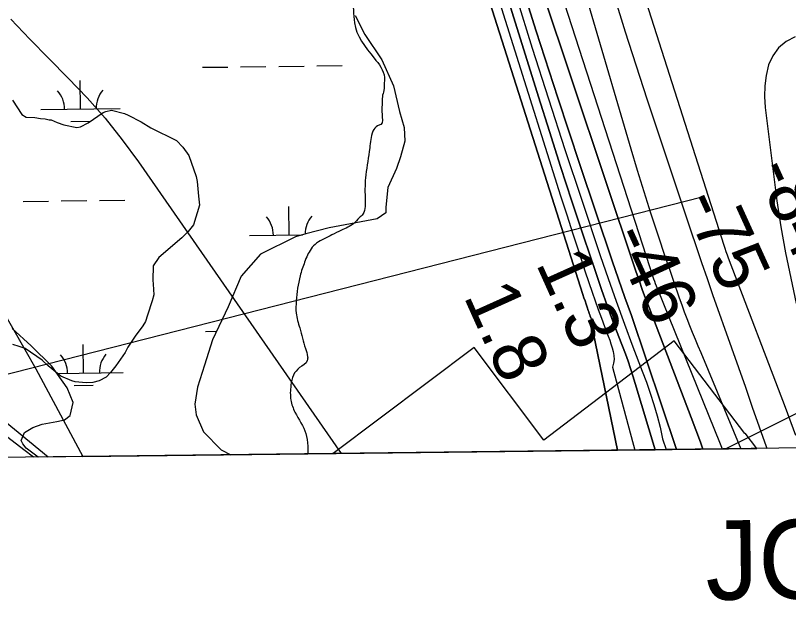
# Model space of a CAD drawing. Extents: x 3694830 to 3732949, y 415201 to 440970.
# Drawn here: x 3716600 to 3717574, y 420616 to 421382 of the extents above; entities that cross this region are included whole.
import ezdxf

# ---------------------------------------------------------------- set-up
doc = ezdxf.new("R2010")
doc.units = 0
for name, color, linetype in [('V-ANNO-TEXT', 7, 'Continuous'), ('V-GRID-FRAM', 7, 'Continuous'), ('V-LEVE-TOET', 7, 'Continuous'), ('V-RIVR-EDGE', 7, 'Continuous'), ('V-RIVR-RANG', 7, 'Continuous'), ('V-RRAP-FSHR', 7, 'Continuous'), ('V-RRAP-RVMT', 7, 'Continuous'), ('V-SITE-VEGE', 7, 'Continuous'), ('V-TOPO-DPTH', 7, 'Continuous'), ('V-TOPO-MAJR', 7, 'Continuous'), ('V-TOPO-MINR', 7, 'Continuous'), ('V-TOPO-WATR', 7, 'Continuous'), ('V-UTIL-LINE', 7, 'Continuous'), ('V-WETL-SWMP', 7, 'Continuous')]:
    doc.layers.add(name, color=color, linetype=linetype)

msp = doc.modelspace()

# ---------------------------------------------------------------- linework, layer by layer
at = {"layer": 'V-GRID-FRAM'}
msp.add_lwpolyline([(3698844.69, 438797.54), (3730590.83, 439176.18), (3730815.62, 420995.11), (3699053.61, 420616.27), (3698844.69, 438797.54)], dxfattribs=at)
at = {"layer": 'V-LEVE-TOET'}
msp.add_lwpolyline([(3716622.87, 420825.82), (3716610.62, 420835.27), (3716590.4, 420850.54)], dxfattribs=at)
at = {"layer": 'V-RIVR-EDGE'}
msp.add_spline([(3716802.17, 421670.49), (3716830.83, 421648.17), (3716851, 421630.33), (3716868.75, 421613.31), (3716887.31, 421596.28), (3716893.75, 421584.94), (3716901.39, 421566.72), (3716910.66, 421552.55), (3716931.23, 421530.25), (3716962.26, 421490.95), (3716975.56, 421470.7), (3716989.66, 421451.26), (3717004.98, 421432.21), (3717019.08, 421411.56), (3717025.9, 421389.3), (3717027.08, 421373.12), (3717052.04, 421328.58), (3717064.92, 421304.29), (3717064.91, 421300.24), (3717064.07, 421287.71), (3717062.43, 421280.03), (3717062, 421269.52), (3717061.97, 421257.79), (3717060.32, 421244.85), (3717056.27, 421243.25), (3717050.6, 421236.39), (3717046.5, 421215.37), (3717041.56, 421181.42), (3717040.68, 421152.71), (3717037.8, 421132.09), (3717033.34, 421127.25), (3717026.45, 421120.39), (3717010.26, 421111.54), (3716998.92, 421105.9), (3716989.2, 421101.07), (3716979.48, 421095.44), (3716972.59, 421088.18), (3716964.46, 421071.62), (3716958.76, 421054.24), (3716953.83, 421022.71), (3716953.79, 421007.35), (3716958.19, 420988.74), (3716965.41, 420962.84), (3716968.21, 420952.32), (3716967.79, 420947.47), (3716958.07, 420938.6), (3716950.36, 420929.31), (3716947.1, 420916.38), (3716947.05, 420897.78), (3716952.27, 420882.4), (3716965.95, 420855.68), (3716968.34, 420839.9), (3716968.61, 420829.95)], degree=3, dxfattribs=at)
at = {"layer": 'V-RIVR-RANG'}
msp.add_line((3716496.26, 420907.04), (3717465.33, 421153.8), dxfattribs=at)
at = {"layer": 'V-RRAP-FSHR'}
for points in [[(3716641.15, 420826.04), (3716497.1, 420943.72), (3716411.63, 421060.5), (3716364.3, 421170.5), (3716321.83, 421303.9), (3716285.1, 421373.79), (3716186.8, 421473.87), (3716066.75, 421590.93), (3715980.47, 421690.03), (3715930.26, 421828.72), (3715913.48, 421896.78), (3715879.02, 422073.91), (3715879.91, 422256.34), (3715873.14, 422428), (3715914.01, 422633.62), (3716031.29, 423135.79), (3716104.08, 423396.54), (3716111.44, 423811.54), (3716102.74, 424148.37), (3716065.57, 424473.12), (3715995.1, 425269.77), (3715894.16, 426351.13), (3715758.55, 427758.05)], [(3716641.15, 420826.04), (3716586.88, 420870.38)]]:
    msp.add_lwpolyline(points, dxfattribs=at)
at = {"layer": 'V-RRAP-RVMT'}
for p, q in [((3717430.39, 420972.28), (3717266.02, 420847.26)), ((3717519.25, 420855.5), (3717430.39, 420972.28)), ((3717178.14, 420964.06), (3717000.43, 420830.33)), ((3717266.02, 420847.26), (3717178.14, 420964.06)), ((3717519.75, 420855.88), (3717519.25, 420855.5)), ((3717534.34, 420836.7), (3717519.75, 420855.88)), ((3717000.43, 420830.33), (3717534.34, 420836.7))]:
    msp.add_line(p, q, dxfattribs=at)
at = {"layer": 'V-SITE-VEGE'}
msp.add_lwpolyline([(3716596.03, 421275.37), (3716607.79, 421257.42), (3716613.36, 421254.32), (3716624.51, 421253.7), (3716631.32, 421252.46), (3716637.51, 421251.84), (3716642.46, 421250.6), (3716644.94, 421250.6), (3716652.37, 421247.51), (3716661.03, 421244.41), (3716677.13, 421241.31), (3716682.08, 421241.93), (3716691.37, 421246.88), (3716710.56, 421259.88), (3716713.66, 421261.12), (3716721.09, 421262.98), (3716737.19, 421258.64), (3716742.14, 421256.79), (3716758.23, 421248.12), (3716770.62, 421240.68), (3716802.81, 421224.58), (3716810.86, 421216.54), (3716818.29, 421206.01), (3716827.57, 421179.39), (3716828.81, 421173.2), (3716830.66, 421154.62), (3716831.9, 421143.48), (3716824.47, 421118.71), (3716817.66, 421110.05), (3716809.61, 421102), (3716780.51, 421077.24), (3716773.7, 421066.71), (3716773.07, 421048.76), (3716773.7, 421043.8), (3716774.31, 421030.18), (3716772.45, 421022.76), (3716766.26, 421004.8), (3716763.78, 420996.75), (3716760.69, 420991.18), (3716750.78, 420978.18), (3716741.49, 420964.56), (3716738.39, 420957.75), (3716726.63, 420941.04), (3716719.82, 420932.37), (3716714.25, 420926.8), (3716705.58, 420921.85), (3716697.53, 420919.99), (3716688.86, 420919.37), (3716675.24, 420920.61), (3716670.91, 420921.85), (3716657.29, 420928.04), (3716652.96, 420931.14), (3716641.19, 420941.04), (3716633.76, 420947.85), (3716612.1, 420962.72), (3716604.67, 420965.19), (3716596.62, 420967.67)], dxfattribs=at)
at = {"layer": 'V-TOPO-DPTH'}
msp.add_line((3717358.94, 420834.6), (3717406.36, 420835.17), dxfattribs=at)
for points in [[(3716812.13, 422663.78), (3716033.9, 421927.76), (3716054.45, 421877.33), (3716064.68, 421852.1), (3716074.85, 421826.84), (3716084.93, 421801.55), (3716094.94, 421776.23), (3716145.42, 421647.95), (3716152.26, 421632.9), (3716160.08, 421618.43), (3716169.35, 421604.85), (3716179.58, 421591.85), (3716198.72, 421570), (3716218.89, 421546.23), (3716238.56, 421522.06), (3716257.47, 421497.3), (3716275.87, 421472.14), (3716402.32, 421293.59), (3716480.92, 421177.25), (3716555.98, 421058.78), (3716625.75, 420937.12), (3716684.91, 420826.56), (3717358.94, 420834.6)], [(3717052.46, 422162.67), (3717076.62, 422065.19), (3717101.54, 421967.9), (3717145.88, 421798.91), (3717149.26, 421786.27), (3717152.71, 421773.64), (3717156.29, 421761.05), (3717159.95, 421748.48), (3717187.93, 421653.93), (3717205.95, 421594.2), (3717224.38, 421534.6), (3717243.45, 421475.21), (3717262.94, 421415.94), (3717382.01, 421060.22), (3717385.96, 421048.66), (3717390.01, 421037.13), (3717394.21, 421025.66), (3717398.52, 421014.22), (3717451.56, 420875.9), (3717463.31, 420844.57), (3717466.51, 420835.89)], [(3717466.51, 420835.89), (3717463.31, 420844.57), (3717451.56, 420875.9), (3717398.52, 421014.22), (3717394.21, 421025.66), (3717390.01, 421037.13), (3717385.96, 421048.66), (3717382.01, 421060.22), (3717262.94, 421415.94), (3717243.45, 421475.21), (3717224.38, 421534.6), (3717205.95, 421594.2), (3717187.93, 421653.93), (3717159.95, 421748.48), (3717156.29, 421761.05), (3717152.71, 421773.64), (3717149.26, 421786.27), (3717145.88, 421798.91), (3717101.54, 421967.9), (3717076.62, 422065.19), (3717052.46, 422162.67)], [(3717087.33, 422109.05), (3717169.89, 421783.26), (3717170.75, 421779.93), (3717171.63, 421776.6), (3717172.54, 421773.29), (3717173.48, 421769.97), (3717181.43, 421742.2), (3717186.45, 421725.02), (3717191.58, 421707.89), (3717196.89, 421690.81), (3717202.31, 421673.77), (3717404.25, 421050.56), (3717405.26, 421047.54), (3717406.32, 421044.53), (3717407.45, 421041.54), (3717408.62, 421038.58), (3717488.3, 420842.58), (3717490.85, 420836.18)], [(3717087.33, 422109.05), (3717169.89, 421783.26), (3717170.75, 421779.93), (3717171.63, 421776.6), (3717172.54, 421773.29), (3717173.48, 421769.97), (3717181.43, 421742.2), (3717186.45, 421725.02), (3717191.58, 421707.89), (3717196.89, 421690.81), (3717202.31, 421673.77), (3717404.25, 421050.56), (3717405.26, 421047.54), (3717406.32, 421044.53), (3717407.45, 421041.54), (3717408.62, 421038.58), (3717488.3, 420842.58), (3717490.85, 420836.18)], [(3717042.79, 422099.17), (3717060.2, 422033.32), (3717077.77, 421967.5), (3717095.45, 421901.72), (3717118.46, 421816.52), (3717124.83, 421793.39), (3717131.34, 421770.3), (3717138.07, 421747.28), (3717144.95, 421724.29), (3717203.62, 421531.46), (3717229.72, 421446.99), (3717256.29, 421362.67), (3717283.57, 421278.58), (3717311.33, 421194.64), (3717352.04, 421073.27), (3717359.95, 421050.19), (3717368.05, 421027.17), (3717376.45, 421004.26), (3717433.29, 420835.49)], [(3717433.29, 420835.49), (3717376.45, 421004.26), (3717368.05, 421027.17), (3717359.95, 421050.19), (3717352.04, 421073.27), (3717311.33, 421194.64), (3717283.57, 421278.58), (3717256.29, 421362.67), (3717229.72, 421446.99), (3717203.62, 421531.46), (3717144.95, 421724.29), (3717138.07, 421747.28), (3717131.34, 421770.3), (3717124.83, 421793.39), (3717118.46, 421816.52), (3717095.45, 421901.72), (3717077.77, 421967.5), (3717060.2, 422033.32), (3717042.79, 422099.17)], [(3717084.18, 421756.32), (3717315.28, 421030.69), (3717316.56, 421026.72), (3717317.85, 421022.74), (3717319.16, 421018.78), (3717320.48, 421014.81), (3717321.92, 421010.56), (3717322.55, 421008.73), (3717323.19, 421006.91), (3717323.85, 421005.1), (3717324.53, 421003.29), (3717325.34, 421001.2), (3717325.61, 421000.43), (3717325.87, 420999.66), (3717326.09, 420998.89), (3717326.3, 420998.1), (3717326.35, 420997.35), (3717326.27, 420996.64), (3717325.96, 420995.99), (3717325.52, 420995.38), (3717358.94, 420834.6)], [(3717358.94, 420834.6), (3717325.52, 420995.38), (3717325.96, 420995.99), (3717326.27, 420996.64), (3717326.35, 420997.35), (3717326.3, 420998.1), (3717326.09, 420998.89), (3717325.87, 420999.66), (3717325.61, 421000.43), (3717325.34, 421001.2), (3717324.53, 421003.29), (3717323.85, 421005.1), (3717323.19, 421006.91), (3717322.55, 421008.73), (3717321.92, 421010.56), (3717320.48, 421014.81), (3717319.16, 421018.78), (3717317.85, 421022.74), (3717316.56, 421026.72), (3717315.28, 421030.69), (3717084.18, 421756.32)], [(3717406.36, 420835.17), (3717380.89, 420918.72), (3717378.2, 420928.11), (3717375.31, 420937.44), (3717372.14, 420946.68), (3717368.78, 420955.85), (3717360.57, 420977.27), (3717353.09, 420997.15), (3717345.77, 421017.09), (3717338.71, 421037.13), (3717331.82, 421057.22), (3717315.97, 421104.37), (3717301.43, 421148.14), (3717287.07, 421191.96), (3717273.01, 421235.88), (3717259.14, 421279.86), (3717128.68, 421698.31)], [(3717406.36, 420835.17), (3717380.89, 420918.72), (3717378.2, 420928.11), (3717375.31, 420937.44), (3717372.14, 420946.68), (3717368.78, 420955.85), (3717360.57, 420977.27), (3717353.09, 420997.15), (3717345.77, 421017.09), (3717338.71, 421037.13), (3717331.82, 421057.22), (3717315.97, 421104.37), (3717301.43, 421148.14), (3717287.07, 421191.96), (3717273.01, 421235.88), (3717259.14, 421279.86), (3717128.68, 421698.31)]]:
    msp.add_lwpolyline(points, dxfattribs=at)
at = {"layer": 'V-TOPO-MAJR'}
msp.add_lwpolyline([(3717228.21, 421715.89), (3717375.73, 421214.18), (3717383.79, 421187.31), (3717392.04, 421160.51), (3717400.57, 421133.79), (3717409.29, 421107.13), (3717419.51, 421076.47), (3717423.3, 421065.2), (3717427.13, 421053.94), (3717431.02, 421042.7), (3717434.95, 421031.48), (3717436.7, 421026.51), (3717439.83, 421017.8), (3717443.03, 421009.11), (3717446.33, 421000.46), (3717449.69, 420991.84), (3717453.12, 420983.25), (3717456.59, 420974.66), (3717460.1, 420966.1), (3717463.64, 420957.55), (3717514.19, 420836.46)], dxfattribs=at)
at = {"layer": 'V-TOPO-MINR'}
for points in [[(3717046.06, 422640.19), (3717272.6, 421796.36), (3717273, 421794.49), (3717273.42, 421792.62), (3717273.85, 421790.76), (3717274.3, 421788.9), (3717280.54, 421763.76), (3717284.26, 421749.37), (3717288.17, 421735.04), (3717292.36, 421720.79), (3717296.74, 421706.59), (3717492.66, 421093.01), (3717494.01, 421088.91), (3717495.4, 421084.84), (3717496.86, 421080.78), (3717498.37, 421076.74), (3717570.19, 420888.94), (3717583.23, 420853.69)], [(3717049.83, 422455.44), (3717293.72, 421617.17), (3717317.57, 421531.71), (3717342.39, 421446.54), (3717368.67, 421361.8), (3717395.92, 421277.36), (3717451.16, 421111.1), (3717457.9, 421091.01), (3717464.71, 421070.94), (3717471.63, 421050.91), (3717478.64, 421030.9), (3717502.35, 420963.75), (3717511.15, 420938.81), (3717519.94, 420913.87), (3717528.72, 420888.93), (3717537.49, 420863.98), (3717546.37, 420839.08), (3717547.18, 420836.85)], [(3717052.46, 422162.67), (3717076.62, 422065.19), (3717101.54, 421967.9), (3717145.88, 421798.91), (3717149.26, 421786.27), (3717152.71, 421773.64), (3717156.29, 421761.05), (3717159.95, 421748.48), (3717187.93, 421653.93), (3717205.95, 421594.2), (3717224.38, 421534.6), (3717243.45, 421475.21), (3717262.94, 421415.94), (3717382.01, 421060.22), (3717385.96, 421048.66), (3717390.01, 421037.13), (3717394.21, 421025.66), (3717398.52, 421014.22), (3717451.56, 420875.9), (3717463.31, 420844.57), (3717466.51, 420835.89)], [(3717087.33, 422109.05), (3717169.89, 421783.26), (3717170.75, 421779.93), (3717171.63, 421776.6), (3717172.54, 421773.29), (3717173.48, 421769.97), (3717181.43, 421742.2), (3717186.45, 421725.02), (3717191.58, 421707.89), (3717196.89, 421690.81), (3717202.31, 421673.77), (3717404.25, 421050.56), (3717405.26, 421047.54), (3717406.32, 421044.53), (3717407.45, 421041.54), (3717408.62, 421038.58), (3717488.3, 420842.58), (3717490.85, 420836.18)], [(3717042.79, 422099.17), (3717060.2, 422033.32), (3717077.77, 421967.5), (3717095.45, 421901.72), (3717118.46, 421816.52), (3717124.83, 421793.39), (3717131.34, 421770.3), (3717138.07, 421747.28), (3717144.95, 421724.29), (3717203.62, 421531.46), (3717229.72, 421446.99), (3717256.29, 421362.67), (3717283.57, 421278.58), (3717311.33, 421194.64), (3717352.04, 421073.27), (3717359.95, 421050.19), (3717368.05, 421027.17), (3717376.45, 421004.26), (3717433.29, 420835.49)], [(3716033.9, 421927.76), (3716054.45, 421877.33), (3716064.68, 421852.1), (3716074.85, 421826.84), (3716084.93, 421801.55), (3716094.94, 421776.23), (3716145.42, 421647.95), (3716152.26, 421632.9), (3716160.08, 421618.43), (3716169.35, 421604.85), (3716179.58, 421591.85), (3716198.72, 421570), (3716218.89, 421546.23), (3716238.56, 421522.06), (3716257.47, 421497.3), (3716275.87, 421472.14), (3716402.32, 421293.59), (3716480.92, 421177.25), (3716555.98, 421058.78), (3716625.75, 420937.12), (3716684.91, 420826.56)], [(3717106.72, 421727.37), (3717287.15, 421154.97), (3717294.76, 421131.05), (3717302.47, 421107.16), (3717310.31, 421083.32), (3717318.25, 421059.5), (3717326.86, 421033.89), (3717330.63, 421022.93), (3717334.48, 421012), (3717338.47, 421001.12), (3717342.55, 420990.28), (3717347.2, 420978.15), (3717348.94, 420973.37), (3717350.57, 420968.55), (3717352.03, 420963.67), (3717353.38, 420958.76), (3717354.18, 420953.84), (3717354.42, 420948.95), (3717353.79, 420944.09), (3717352.59, 420939.25), (3717380.53, 420834.86)], [(3717128.68, 421698.31), (3717259.14, 421279.86), (3717273.01, 421235.88), (3717287.07, 421191.96), (3717301.43, 421148.14), (3717315.97, 421104.37), (3717331.82, 421057.22), (3717338.71, 421037.13), (3717345.77, 421017.09), (3717353.09, 420997.15), (3717360.57, 420977.27), (3717368.78, 420955.85), (3717372.14, 420946.68), (3717375.31, 420937.44), (3717378.2, 420928.11), (3717380.89, 420918.72), (3717406.36, 420835.17)], [(3717231.29, 421405.34), (3717251.33, 421341.18), (3717271.68, 421277.12), (3717292.51, 421213.22), (3717313.67, 421149.42), (3717337.04, 421079.8), (3717346.93, 421050.95), (3717357.07, 421022.19), (3717367.56, 420993.56), (3717378.3, 420965.02), (3717390.05, 420934.36), (3717395.2, 420920.39), (3717400.09, 420906.34), (3717404.61, 420892.16), (3717408.89, 420877.9), (3717412.53, 420863.5), (3717415.59, 420848.99), (3717420, 420835.33)], [(3716593.94, 421377.47), (3716617.86, 421352.55), (3716642.07, 421327.89), (3716666.46, 421303.42), (3716690.26, 421278.47), (3716713.11, 421252.72), (3716734.52, 421225.77), (3716754.98, 421198.01), (3717010.58, 420830.45)], [(3717582.78, 421355.41), (3717571.42, 421349.35), (3717561.76, 421341.69), (3717554.65, 421331.61), (3717549.25, 421319.92), (3717546.24, 421306.71), (3717544.33, 421293.41), (3717544.09, 421279.98), (3717544.95, 421266.46), (3717559.79, 421148.86), (3717562.07, 421132.4), (3717564.61, 421115.99), (3717567.53, 421099.64), (3717570.72, 421083.33), (3717583.99, 421019.48)]]:
    msp.add_lwpolyline(points, dxfattribs=at)
at = {"layer": 'V-TOPO-WATR'}
msp.add_lwpolyline([(3717084.18, 421756.32), (3717315.28, 421030.69), (3717316.56, 421026.72), (3717317.85, 421022.74), (3717319.16, 421018.78), (3717320.48, 421014.81), (3717321.92, 421010.56), (3717322.55, 421008.73), (3717323.19, 421006.91), (3717323.85, 421005.1), (3717324.53, 421003.29), (3717325.34, 421001.2), (3717325.61, 421000.43), (3717325.87, 420999.66), (3717326.09, 420998.89), (3717326.3, 420998.1), (3717326.35, 420997.35), (3717326.27, 420996.64), (3717325.96, 420995.99), (3717325.52, 420995.38), (3717358.94, 420834.6)], dxfattribs=at)
at = {"layer": 'V-UTIL-LINE'}
msp.add_line((3717494.77, 420836.22), (3719291.83, 421734.75), dxfattribs=at)
at = {"layer": 'V-WETL-SWMP'}
for p, q in [((3717028.09, 421382.25), (3717040.21, 421358.44)), ((3717040.21, 421358.44), (3717061.59, 421326.43)), ((3717061.59, 421326.43), (3717076.54, 421293.46)), ((3716835.71, 421316.93), (3716867.71, 421317.31)), ((3716883.71, 421317.51), (3716915.7, 421317.89)), ((3716931.7, 421318.08), (3716963.7, 421318.46)), ((3716979.7, 421318.65), (3717011.7, 421319.03)), ((3716681.74, 421264.35), (3716681.31, 421300.35)), ((3717076.54, 421293.46), (3717084.13, 421261.35)), ((3716631.74, 421263.75), (3716731.73, 421264.95)), ((3717084.13, 421261.35), (3717089.79, 421241.17)), ((3716669.92, 421248.78), (3716693.92, 421249.06)), ((3717089.79, 421241.17), (3717090.84, 421223.72)), ((3717090.84, 421223.72), (3717085.47, 421204.38)), ((3717085.47, 421204.38), (3717080.06, 421189.63)), ((3717080.06, 421189.63), (3717069.21, 421165.66)), ((3717069.21, 421165.66), (3717066.64, 421140.82)), ((3716609.71, 421148.05), (3716641.71, 421148.43)), ((3716657.71, 421148.62), (3716689.7, 421149.01)), ((3716705.7, 421149.2), (3716737.7, 421149.58)), ((3716945.08, 421105.62), (3716944.65, 421141.62)), ((3717066.64, 421140.82), (3717066.7, 421133.47)), ((3717055.72, 421126.04), (3716995.15, 421114.56)), ((3717066.7, 421133.47), (3717055.72, 421126.04)), ((3716895.09, 421105.02), (3716961.81, 421105.82)), ((3716965.8, 421106.99), (3716952.96, 421103.22)), ((3716995.15, 421114.56), (3716965.8, 421106.99)), ((3716952.96, 421103.22), (3716909, 421081.75)), ((3716909, 421081.75), (3716884.39, 421054)), ((3716884.39, 421054), (3716868.14, 421015.28)), ((3716868.14, 421015.28), (3716848.23, 420973.77)), ((3716619.71, 420966.21), (3716595.66, 420988.09)), ((3716839.68, 420984.28), (3716853.35, 420984.44)), ((3716848.23, 420973.77), (3716838.36, 420941.53)), ((3716645.64, 420940.67), (3716619.71, 420966.21)), ((3716685.71, 420931.7), (3716685.28, 420967.7)), ((3716665.14, 420913.24), (3716645.64, 420940.67)), ((3716838.36, 420941.53), (3716829.37, 420913.89)), ((3716652.3, 420931.3), (3716735.7, 420932.3)), ((3716672.63, 420894.91), (3716665.14, 420913.24)), ((3716673.89, 420916.13), (3716697.89, 420916.41)), ((3716829.37, 420913.89), (3716825.85, 420892.73)), ((3716669.08, 420878.34), (3716672.63, 420894.91)), ((3716825.85, 420892.73), (3716827.79, 420878.96)), ((3716652.13, 420870.87), (3716661.77, 420872.78)), ((3716661.77, 420872.78), (3716669.08, 420878.34)), ((3716827.79, 420878.96), (3716837.14, 420857.89)), ((3716611.34, 420856.78), (3716621.86, 420863.29)), ((3716621.86, 420863.29), (3716633.78, 420867.51)), ((3716633.78, 420867.51), (3716652.13, 420870.87)), ((3716607.28, 420846.64), (3716610.43, 420854.93)), ((3716610.43, 420854.93), (3716611.34, 420856.78)), ((3716837.14, 420857.89), (3716859.37, 420835.08)), ((3716609.15, 420842.52), (3716607.28, 420846.64)), ((3716613.32, 420837.03), (3716609.15, 420842.52)), ((3716628.52, 420825.89), (3716613.32, 420837.03)), ((3716859.37, 420835.08), (3716871.33, 420828.79)), ((3716871.33, 420828.79), (3716628.52, 420825.89))]:
    msp.add_line(p, q, dxfattribs=at)
for centre, start, end in [((3716626.49, 421264.17), 359.91153, 41.45518), ((3716736.97, 421265.48), 139.91153, 181.45519), ((3716889.84, 421105.43), 359.91153, 41.45518), ((3717000.32, 421106.75), 139.91153, 179.9618), ((3716630.46, 420931.52), 359.91153, 41.45518), ((3716740.94, 420932.83), 139.91153, 181.45519)]:
    msp.add_arc(centre, 35.25, start, end, dxfattribs=at)

# ---------------------------------------------------------------- texts
at = {"layer": 'V-ANNO-TEXT'}
msp.add_text('JOINS SHEET 59', height=100, rotation=0.68333, dxfattribs=at).set_placement((3717470.24, 420645.92))
at = {"layer": 'V-RIVR-RANG'}
for s, rotation, p in [('-84', 294.49231, (3717530.95, 421187.71)), ('-75', 294.49231, (3717439.3, 421147.68)), ('-46', 294.49231, (3717349.07, 421104.53)), ('1.3', 294.20833, (3717255.33, 421070.1)), ('1.8', 294.20833, (3717164.22, 421028.87))]:
    msp.add_text(s, height=67, rotation=rotation, dxfattribs=at).set_placement(p)

doc.saveas('drawing.dxf')
